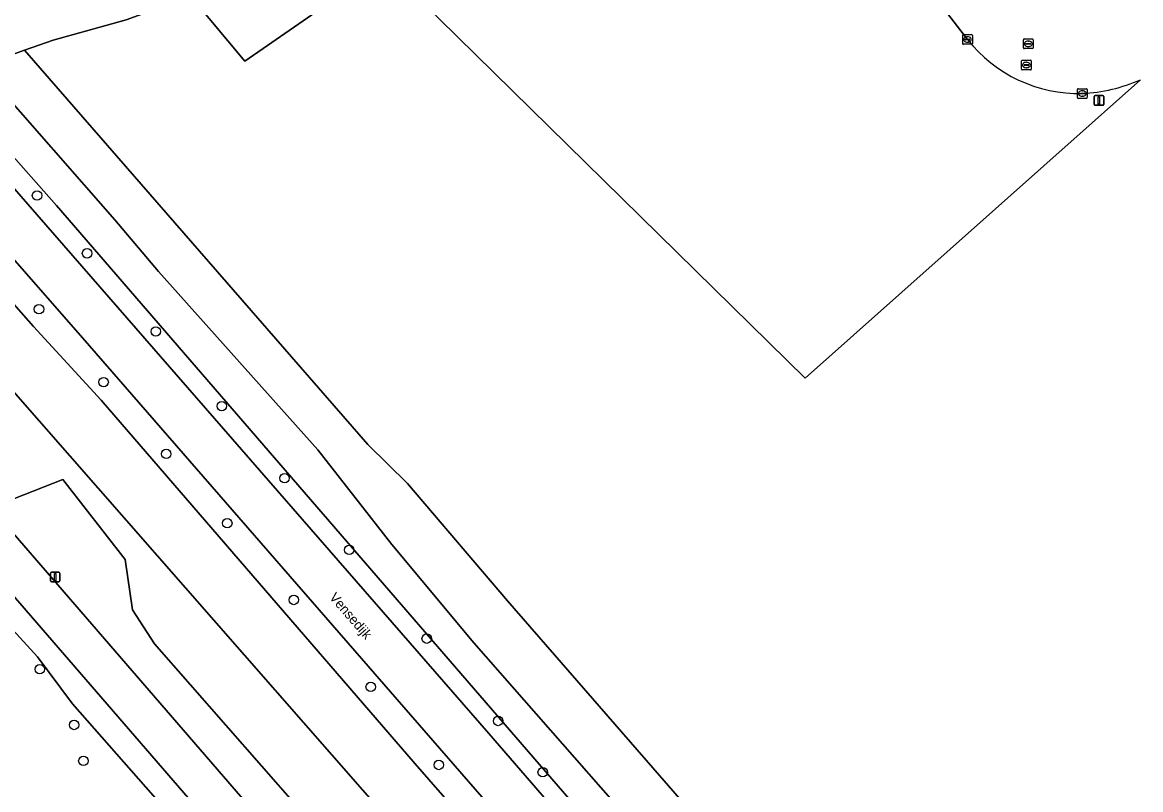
# Model space of a CAD drawing. Extents: x 155209 to 156748, y 385356 to 388487.
# Drawn here: x 155851.5 to 155966.9, y 385615.9 to 385695.1 of the extents above; entities that cross this region are included whole.
import ezdxf

# ---------------------------------------------------------------- set-up
doc = ezdxf.new("R2010")
doc.units = 0
for name, color, linetype in [('IMGEO_Berm_groen', 7, 'Continuous'), ('IMGEO_Boom', 7, 'Continuous'), ('IMGEO_Fietspad_gesloten', 7, 'Continuous'), ('IMGEO_Gemengd_bos', 7, 'Continuous'), ('IMGEO_Groenvoorziening', 7, 'Continuous'), ('IMGEO_Inrit_halfverhard', 7, 'Continuous'), ('IMGEO_Kolk', 7, 'Continuous'), ('IMGEO_Lichtmast', 7, 'Continuous'), ('IMGEO_Loofbos', 7, 'Continuous'), ('IMGEO_Openbare_ruimte_label', 7, 'Continuous'), ('IMGEO_Rijbaan_lokaal_gesloten', 7, 'Continuous'), ('IMGEO_Rioolput', 7, 'Continuous')]:
    doc.layers.add(name, color=color, linetype=linetype)

msp = doc.modelspace()

# ---------------------------------------------------------------- linework, layer by layer
at = {"layer": 'IMGEO_Berm_groen'}
for points in [[(155782.07, 385749.03), (155782.06, 385749.04), (155781.96, 385748.95), (155782.85, 385747.95), (155780.5, 385745.88), (155787.45, 385737.87), (155791.34, 385733.72), (155816.07, 385705.59), (155827.38, 385692.36), (155852.69, 385663.67), (155859.69, 385656.07), (155892.08, 385618.52), (155930.14, 385574.84), (155959.32, 385541.34), (155963.31, 385536.34), (155969.74, 385527.64)], [(155953.55, 385552.36), (155932.32, 385576.76), (155858.46, 385661.65), (155782.07, 385749.03)], [(155777.86, 385715.13), (155782.52, 385709.35), (155785.67, 385706.23), (155793.08, 385698.9), (155800.98, 385689.95), (155804.16, 385686.65), (155806.27, 385683.98), (155807.67, 385681.86), (155810.16, 385678.73), (155813.26, 385675.28), (155814.49, 385673.96), (155824.14, 385662.7), (155832.07, 385653.89), (155839, 385645.25), (155843.23, 385640.36), (155844.26, 385638.91), (155847.26, 385635.93), (155853.11, 385629.55), (155856.72, 385624.72), (155874.64, 385604.33), (155875.73, 385602.78), (155900.15, 385574.95), (155913.21, 385559.93), (155965.33, 385500)], [(155915.04, 385561.54), (155881.17, 385600.52), (155801.14, 385693.08)], [(155883.59, 385609.91), (155865.17, 385630.9), (155862.9, 385634.42), (155862.16, 385639.6), (155855.72, 385647.87), (155850.73, 385645.9), (155838.97, 385661.71), (155833.46, 385670.65), (155827.75, 385672.6), (155823.98, 385678.66), (155814.67, 385686.66), (155815.7, 385682.65), (155885.24, 385602.25)]]:
    msp.add_lwpolyline(points, dxfattribs=at)
msp.add_lwpolyline([(155886.95, 385639.23), (155855.07, 385676.14), (155845.61, 385686.83), (155844.88, 385684.53), (155899.68, 385621.64), (155918.84, 385599.48), (155936.02, 385580.01), (155937.21, 385581.04)], close=True, dxfattribs=at)
at = {"layer": 'IMGEO_Boom'}
for centre in [(155853.06, 385677.18), (155858.22, 385671.21), (155853.26, 385665.44), (155865.31, 385663.15), (155859.93, 385657.92), (155872.12, 385655.44), (155866.39, 385650.51), (155878.6, 385648), (155872.69, 385643.35), (155885.27, 385640.6), (155879.55, 385635.43), (155893.27, 385631.44), (155853.34, 385628.28), (155887.49, 385626.46), (155856.88, 385622.53), (155900.64, 385622.94), (155857.84, 385618.82), (155894.51, 385618.4), (155905.24, 385617.65)]:
    msp.add_circle(centre, 0.489, dxfattribs=at)
at = {"layer": 'IMGEO_Fietspad_gesloten'}
msp.add_lwpolyline([(155801.14, 385693.08), (155881.17, 385600.52), (155915.04, 385561.54), (155918.18, 385564.31), (155885.24, 385602.25), (155815.7, 385682.65)], dxfattribs=at)
at = {"layer": 'IMGEO_Gemengd_bos'}
for points in [[(155966.94, 385689.13), (155932.32, 385658.31), (155888.87, 385701.04), (155874.49, 385691.04), (155869.08, 385697.58), (155868.93, 385697.76), (155862.24, 385695.33), (155854.73, 385693.22), (155851.78, 385692.17), (155887.19, 385651.49), (155891.3, 385647.45), (155901.59, 385635.34), (155927.68, 385605.37), (155943.93, 385586.89), (155954.72, 385574.62), (155959.07, 385569.83), (155978.29, 385550.24)], [(155978.29, 385550.24), (155959.07, 385569.83), (155954.72, 385574.62), (155943.93, 385586.89), (155927.68, 385605.37), (155901.59, 385635.34), (155891.3, 385647.45), (155887.19, 385651.49), (155851.78, 385692.17), (155850.05, 385691.56), (155847.34, 385690.32), (155848.14, 385689.39), (155861.07, 385674.68), (155865.58, 385669.32), (155882.05, 385650.94), (155889.67, 385641.14), (155898.13, 385630.99), (155939.92, 385583.4), (155949.78, 385572.17), (156000, 385516.89)]]:
    msp.add_lwpolyline(points, dxfattribs=at)
at = {"layer": 'IMGEO_Groenvoorziening'}
for points in [[(155859.69, 385656.07), (155852.69, 385663.67), (155827.38, 385692.36), (155816.07, 385705.59), (155791.34, 385733.72), (155787.45, 385737.87), (155780.5, 385745.88), (155778.36, 385743.99), (155782.11, 385737.88), (155784.14, 385735.45), (155786.95, 385731.61), (155788.09, 385730.32), (155789.13, 385728.5), (155796.23, 385719.42), (155812.62, 385700.37), (155814.03, 385698.73), (155925.85, 385571.06), (155957.92, 385534.44), (155959.32, 385541.34), (155930.14, 385574.84), (155892.08, 385618.52)], [(155865.58, 385669.32), (155861.07, 385674.68), (155848.14, 385689.39), (155847.34, 385690.32), (155846.63, 385689.99), (155845.61, 385686.83), (155855.07, 385676.14), (155886.95, 385639.23), (155937.21, 385581.04), (155939.92, 385583.4), (155898.13, 385630.99), (155889.67, 385641.14), (155882.05, 385650.94)]]:
    msp.add_lwpolyline(points, close=True, dxfattribs=at)
for points in [[(155949.08, 385693.29), (155937.24, 385708.71), (155927.17, 385721.74), (155921.49, 385716.23)], [(155882.85, 385702.81), (155868.93, 385697.76), (155869.08, 385697.58), (155874.49, 385691.04), (155888.87, 385701.04), (155932.32, 385658.31), (155966.94, 385689.13)], [(155925.85, 385571.06), (155814.03, 385698.73), (155812.62, 385700.37), (155810.49, 385696.79), (155814.43, 385690.98), (155820.27, 385686.8), (155823.21, 385684.03), (155823.98, 385678.66), (155827.75, 385672.6), (155833.46, 385670.65), (155838.97, 385661.71), (155850.73, 385645.9), (155855.72, 385647.87), (155862.16, 385639.6), (155862.9, 385634.42), (155865.17, 385630.9), (155883.59, 385609.91)]]:
    msp.add_lwpolyline(points, dxfattribs=at)
for centre, radius, start, end in [((155960.59, 385702.35), 14.65, 218.2113, 271.2862), ((155959.89, 385705.46), 17.79, 273.292, 293.33)]:
    msp.add_arc(centre, radius, start, end, dxfattribs=at)
at = {"layer": 'IMGEO_Inrit_halfverhard'}
msp.add_lwpolyline([(155833.92, 385697.1), (155834.55, 385696.38), (155844.88, 385684.53), (155845.61, 385686.83), (155846.63, 385689.99), (155847.34, 385690.32), (155850.05, 385691.56), (155851.78, 385692.17), (155854.73, 385693.22), (155862.24, 385695.33), (155868.93, 385697.76)], dxfattribs=at)
at = {"layer": 'IMGEO_Kolk'}
for p, q in [((155948.58, 385692.86), (155948.58, 385693.71)), ((155948.65, 385693.79), (155949.51, 385693.79)), ((155949.51, 385692.79), (155948.65, 385692.79)), ((155948.84, 385693.28), (155948.84, 385693.29)), ((155948.88, 385693.33), (155949.28, 385693.33)), ((155949.27, 385693.24), (155948.88, 385693.24)), ((155949.09, 385693.01), (155949.06, 385693.01)), ((155949.07, 385693.57), (155949.09, 385693.57)), ((155949.32, 385693.29), (155949.32, 385693.28)), ((155949.58, 385693.71), (155949.58, 385692.86)), ((155960.49, 385688.2), (155961.34, 385688.2)), ((155960.42, 385687.28), (155960.42, 385688.13)), ((155961.34, 385687.2), (155960.49, 385687.2)), ((155960.67, 385687.7), (155960.67, 385687.71)), ((155961.11, 385687.66), (155960.71, 385687.66)), ((155960.72, 385687.75), (155961.11, 385687.75)), ((155960.9, 385687.98), (155960.93, 385687.98)), ((155960.93, 385687.42), (155960.9, 385687.42)), ((155961.16, 385687.71), (155961.16, 385687.7)), ((155961.42, 385688.13), (155961.42, 385687.28))]:
    msp.add_line(p, q, dxfattribs=at)
for points in [[(155948.58, 385692.86), (155948.58, 385693.71)], [(155948.65, 385693.79), (155949.51, 385693.79)], [(155949.51, 385692.79), (155948.65, 385692.79)], [(155949.58, 385693.71), (155949.58, 385692.86)], [(155960.49, 385688.2), (155961.34, 385688.2)], [(155960.42, 385687.28), (155960.42, 385688.13)], [(155961.34, 385687.2), (155960.49, 385687.2)], [(155961.42, 385688.13), (155961.42, 385687.28)]]:
    msp.add_lwpolyline(points, dxfattribs=at)
for centre, radius, start, end in [((155948.65, 385693.71), 0.0765, 91.552, 178.448), ((155948.65, 385693.71), 0.0765, 91.552, 178.448), ((155948.65, 385692.86), 0.0765, 181.552, 268.448), ((155948.65, 385692.86), 0.0765, 181.552, 268.448), ((155948.88, 385693.29), 0.0403, 85.8775, 175.7526), ((155948.87, 385693.28), 0.0366, 178.938, 274.7102), ((155949.28, 385693.29), 0.043, 264.8664, 352.4533), ((155949.28, 385693.29), 0.0386, 1.7309, 96.639), ((155949.5, 385693.71), 0.0765, 1.552, 88.448), ((155949.5, 385693.71), 0.0765, 1.552, 88.448), ((155949.5, 385692.86), 0.0765, 271.552, 358.448), ((155949.5, 385692.86), 0.0765, 271.552, 358.448), ((155960.49, 385688.13), 0.0765, 91.552, 178.448), ((155960.49, 385688.13), 0.0765, 91.552, 178.448), ((155961.34, 385688.13), 0.0765, 1.552, 88.448), ((155961.34, 385688.13), 0.0765, 1.552, 88.448), ((155960.49, 385687.28), 0.0765, 181.552, 268.448), ((155960.49, 385687.28), 0.0765, 181.552, 268.448), ((155960.71, 385687.71), 0.0403, 85.8775, 175.7526), ((155960.71, 385687.7), 0.0366, 178.938, 274.7102), ((155961.12, 385687.71), 0.0386, 1.7309, 96.639), ((155961.12, 385687.7), 0.043, 264.8664, 352.4533), ((155961.34, 385687.28), 0.0765, 271.552, 358.448), ((155961.34, 385687.28), 0.0765, 271.552, 358.448)]:
    msp.add_arc(centre, radius, start, end, dxfattribs=at)
for centre, major_axis, ratio, start_param, end_param in [((155949.07, 385693.29), (-0.387, 0.002), 0.722429, 4.712389, 7.853982), ((155949.09, 385693.29), (-0.39, 0.002), 0.717154, 1.570796, 4.712389), ((155960.9, 385687.7), (-0.387, 0.002), 0.722429, 4.712389, 7.853982), ((155960.93, 385687.7), (-0.39, 0.002), 0.717154, 1.570796, 4.712389)]:
    msp.add_ellipse(centre, major_axis=major_axis, ratio=ratio, start_param=start_param, end_param=end_param, dxfattribs=at)
at = {"layer": 'IMGEO_Lichtmast'}
for p, q in [((155962.14, 385686.59), (155962.14, 385687.39)), ((155962.14, 385687.39), (155962.14, 385686.59)), ((155962.24, 385687.49), (155963.03, 385687.49)), ((155963.03, 385687.49), (155962.24, 385687.49)), ((155963.13, 385687.39), (155963.13, 385686.59)), ((155963.13, 385686.59), (155963.13, 385687.39)), ((155963.03, 385686.49), (155962.24, 385686.49)), ((155962.24, 385686.49), (155963.03, 385686.49)), ((155854.44, 385637.4), (155854.44, 385638.19)), ((155854.44, 385638.19), (155854.44, 385637.4)), ((155854.54, 385638.29), (155855.32, 385638.29)), ((155855.32, 385638.29), (155854.54, 385638.29)), ((155855.42, 385638.19), (155855.42, 385637.4)), ((155855.42, 385637.4), (155855.42, 385638.19)), ((155855.32, 385637.3), (155854.54, 385637.3)), ((155854.54, 385637.3), (155855.32, 385637.3))]:
    msp.add_line(p, q, dxfattribs=at)
for points in [[(155962.56, 385687.36), (155962.71, 385687.36), (155962.71, 385686.61), (155962.56, 385686.61), (155962.56, 385687.36)], [(155854.85, 385638.17), (155855.01, 385638.17), (155855.01, 385637.42), (155854.85, 385637.42), (155854.85, 385638.17)]]:
    msp.add_lwpolyline(points, dxfattribs=at)
for centre, start, end in [((155962.24, 385687.39), 90, 180), ((155962.24, 385687.39), 90, 180), ((155963.03, 385687.39), 0, 90), ((155963.03, 385687.39), 360, 90), ((155962.24, 385686.59), 180, 270), ((155962.24, 385686.59), 180, 270), ((155963.03, 385686.59), 270, 0), ((155963.03, 385686.59), 270, 0), ((155854.54, 385638.19), 90, 180), ((155854.54, 385638.19), 90, 180), ((155855.32, 385638.19), 0, 90), ((155855.32, 385638.19), 360, 90), ((155854.54, 385637.4), 180, 270), ((155854.54, 385637.4), 180, 270), ((155855.32, 385637.4), 270, 0), ((155855.32, 385637.4), 270, 0)]:
    msp.add_arc(centre, 0.1, start, end, dxfattribs=at)
at = {"layer": 'IMGEO_Loofbos'}
msp.add_lwpolyline([(155972.92, 385492.24), (155965.33, 385500), (155913.21, 385559.93), (155900.15, 385574.95), (155875.73, 385602.78), (155874.64, 385604.33), (155856.72, 385624.72), (155853.11, 385629.55), (155847.26, 385635.93), (155844.26, 385638.91), (155843.23, 385640.36), (155839, 385645.25), (155832.07, 385653.89), (155824.14, 385662.7), (155814.49, 385673.96), (155807.18, 385667.54), (155806.1, 385668.83), (155813.26, 385675.28), (155810.16, 385678.73), (155807.67, 385681.86)], dxfattribs=at)
at = {"layer": 'IMGEO_Rijbaan_lokaal_gesloten'}
for points in [[(155900.76, 385766.21), (155895.64, 385762.28), (155925.84, 385723.45), (155927.17, 385721.74), (155937.24, 385708.71), (155949.08, 385693.29)], [(155959.1, 385553.69), (155950.77, 385563.31), (155936.02, 385580.01), (155918.84, 385599.48), (155899.68, 385621.64), (155844.88, 385684.53), (155834.55, 385696.38), (155833.92, 385697.1), (155810.7, 385723.74), (155790.5, 385746.92), (155787.77, 385749.85), (155787.5, 385750.14), (155787.41, 385750.24), (155785.71, 385752.29), (155782.06, 385749.04), (155782.07, 385749.03), (155858.46, 385661.65), (155932.32, 385576.76), (155953.55, 385552.36)]]:
    msp.add_lwpolyline(points, dxfattribs=at)
for centre, radius, start, end in [((155960.59, 385702.35), 14.65, 218.2113, 271.2862), ((155959.89, 385705.46), 17.79, 273.292, 293.33)]:
    msp.add_arc(centre, radius, start, end, dxfattribs=at)
at = {"layer": 'IMGEO_Rioolput'}
for p, q in [((155954.84, 385692.41), (155954.84, 385693.26)), ((155954.92, 385693.34), (155955.77, 385693.34)), ((155955.1, 385692.83), (155955.1, 385692.84)), ((155955.54, 385692.79), (155955.14, 385692.79)), ((155955.15, 385692.88), (155955.54, 385692.88)), ((155955.33, 385693.12), (155955.36, 385693.12)), ((155955.59, 385692.84), (155955.59, 385692.83)), ((155955.85, 385693.26), (155955.85, 385692.41)), ((155955.77, 385692.34), (155954.92, 385692.34)), ((155955.35, 385692.56), (155955.33, 385692.56)), ((155954.66, 385690.22), (155954.66, 385691.07)), ((155954.73, 385691.15), (155955.58, 385691.15)), ((155954.91, 385690.64), (155954.91, 385690.65)), ((155955.35, 385690.6), (155954.95, 385690.6)), ((155954.96, 385690.69), (155955.36, 385690.69)), ((155955.14, 385690.93), (155955.17, 385690.93)), ((155955.4, 385690.65), (155955.4, 385690.64)), ((155955.66, 385691.07), (155955.66, 385690.22)), ((155955.58, 385690.15), (155954.73, 385690.15)), ((155955.17, 385690.37), (155955.14, 385690.37))]:
    msp.add_line(p, q, dxfattribs=at)
for points in [[(155954.84, 385692.41), (155954.84, 385693.26)], [(155954.92, 385693.34), (155955.77, 385693.34)], [(155955.85, 385693.26), (155955.85, 385692.41)], [(155955.77, 385692.34), (155954.92, 385692.34)], [(155954.66, 385690.22), (155954.66, 385691.07)], [(155954.73, 385691.15), (155955.58, 385691.15)], [(155955.66, 385691.07), (155955.66, 385690.22)], [(155955.58, 385690.15), (155954.73, 385690.15)]]:
    msp.add_lwpolyline(points, dxfattribs=at)
for centre, radius, start, end in [((155954.92, 385693.26), 0.0765, 91.552, 178.448), ((155954.92, 385693.26), 0.0765, 91.552, 178.448), ((155955.14, 385692.84), 0.0403, 85.8775, 175.7526), ((155955.14, 385692.83), 0.0366, 178.938, 274.7102), ((155955.55, 385692.84), 0.0386, 1.7309, 96.639), ((155955.54, 385692.84), 0.043, 264.8664, 352.4533), ((155955.77, 385693.26), 0.0765, 1.552, 88.448), ((155955.77, 385693.26), 0.0765, 1.552, 88.448), ((155954.92, 385692.41), 0.0765, 181.552, 268.448), ((155954.92, 385692.41), 0.0765, 181.552, 268.448), ((155955.77, 385692.41), 0.0765, 271.552, 358.448), ((155955.77, 385692.41), 0.0765, 271.552, 358.448), ((155954.73, 385691.07), 0.0765, 91.552, 178.448), ((155954.73, 385691.07), 0.0765, 91.552, 178.448), ((155954.96, 385690.65), 0.0403, 85.8775, 175.7526), ((155954.95, 385690.64), 0.0366, 178.938, 274.7102), ((155955.36, 385690.65), 0.043, 264.8664, 352.4533), ((155955.36, 385690.65), 0.0386, 1.7309, 96.639), ((155955.58, 385691.07), 0.0765, 1.552, 88.448), ((155955.58, 385691.07), 0.0765, 1.552, 88.448), ((155954.73, 385690.22), 0.0765, 181.552, 268.448), ((155954.73, 385690.22), 0.0765, 181.552, 268.448), ((155955.58, 385690.22), 0.0765, 271.552, 358.448), ((155955.58, 385690.22), 0.0765, 271.552, 358.448)]:
    msp.add_arc(centre, radius, start, end, dxfattribs=at)
for centre, major_axis, ratio, start_param, end_param in [((155955.33, 385692.84), (-0.387, 0.002), 0.722429, 4.712389, 7.853982), ((155955.36, 385692.84), (-0.39, 0.002), 0.717154, 1.570796, 4.712389), ((155955.14, 385690.65), (-0.387, 0.002), 0.722429, 4.712389, 7.853982), ((155955.17, 385690.65), (-0.39, 0.002), 0.717154, 1.570796, 4.712389)]:
    msp.add_ellipse(centre, major_axis=major_axis, ratio=ratio, start_param=start_param, end_param=end_param, dxfattribs=at)

# ---------------------------------------------------------------- texts
at = {"layer": 'IMGEO_Openbare_ruimte_label'}
msp.add_text('Vensedijk', height=1, rotation=310.9865, dxfattribs=at).set_placement((155883.16, 385635.66))

doc.saveas('drawing.dxf')
